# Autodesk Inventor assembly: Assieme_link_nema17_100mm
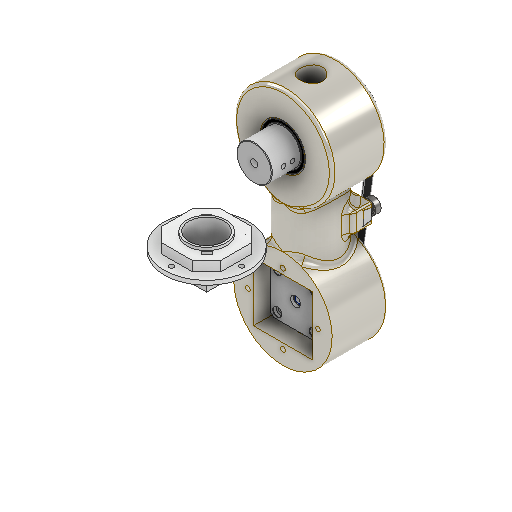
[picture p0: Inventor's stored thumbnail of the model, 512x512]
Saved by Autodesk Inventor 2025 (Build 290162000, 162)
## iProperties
Created: 2025-05
Part Number: Assieme_link_nema17_100mm
Document SubType Name: Assembly
Designer: 18907419
Author: 18907419
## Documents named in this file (10)
- C:\Users\R5800u\Desktop\robot v3\Assieme_link_nema17_100mm.iam
- C:\Users\R5800u\Desktop\robot v3\NEMA_14-13mm.iam
- C:\Users\R5800u\Desktop\robot v3\gt2-60.ipt
- C:\Users\R5800u\Desktop\robot v3\cinghia.ipt
- C:\Users\R5800u\Desktop\robot v3\blocco_tendi.ipt
- C:\Users\R5800u\Documents\Inventor\Content Center Files\R2025\it-IT\BS 290 SKF(30)\BS 290 SKF - SKF 623.ipt
- C:\Users\R5800u\Desktop\robot v3\6705-2RS.ipt
- C:\Users\R5800u\Documents\Inventor\Content Center Files\R2025\it-IT\AS 1420\AS 1420 - 1973 - M3 x 6.ipt
- C:\Users\R5800u\Desktop\robot v3\blocco_nema17.ipt
- C:\Users\R5800u\Desktop\robot v3\blocco_quadrato.ipt
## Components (10 placed, 9 different names)
1. blocco_nema17:1 — Coincidente:64, Allineato:11, Coincidente:65, Coincidente:66, Coincidente:67, Allineato:14, Rotazionale:25, Rotazionale:26, Coincidente:74, Rigido:1, Angolo:1
2. NEMA_14HM11-0404S:4 [sub-assembly] — Coincidente:66, Coincidente:67, Coincidente:73, Allineato:15
3. cinghia:1 — Coincidente:73, Coincidente:76, Allineato:16
4. blocco_tendi:1 — Allineato:14, Rigido:1, Rotazionale:27
5. 6705-2RS:3 — Rotazionale:25
6. 6705-2RS:4 — Rotazionale:26, Coincidente:75
7. gt2-60:1 — Coincidente:74, Coincidente:75, Allineato:15, Coincidente:76, Angolo:1, Allineato:16
8. BS 290 SKF 623:1 — Rotazionale:27
9. AS 1420 - Metrico M3 x 6:1
10. blocco_quadrato:1
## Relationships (17: Mate 8, Flush 4, RevoluteJoint 3, WeldJoint 1, Angle 1)
- Coincidente:64 [Mate]: blocco_nema17:1
- Allineato:11 [Flush]: blocco_nema17:1
- Coincidente:65 [Mate]: blocco_nema17:1
- Coincidente:66 [Mate]: blocco_nema17:1 ↔ NEMA_14HM11-0404S:4
- Coincidente:67 [Mate]: blocco_nema17:1 ↔ NEMA_14HM11-0404S:4
- Allineato:14 [Flush]: blocco_nema17:1 ↔ blocco_tendi:1
- Rotazionale:25 [RevoluteJoint]: blocco_nema17:1 ↔ 6705-2RS:3
- Coincidente:73 [Mate]: NEMA_14HM11-0404S:4 ↔ cinghia:1
- Rotazionale:26 [RevoluteJoint]: blocco_nema17:1 ↔ 6705-2RS:4
- Coincidente:74 [Mate]: blocco_nema17:1 ↔ gt2-60:1
- Coincidente:75 [Mate]: 6705-2RS:4 ↔ gt2-60:1
- Allineato:15 [Flush]: NEMA_14HM11-0404S:4 ↔ gt2-60:1
- Coincidente:76 [Mate]: cinghia:1 ↔ gt2-60:1
- Rigido:1 [WeldJoint]: blocco_nema17:1 ↔ blocco_tendi:1
- Angolo:1 [Angle]: blocco_nema17:1 ↔ gt2-60:1
- Allineato:16 [Flush]: cinghia:1 ↔ gt2-60:1
- Rotazionale:27 [RevoluteJoint]: blocco_tendi:1 ↔ BS 290 SKF 623:1
